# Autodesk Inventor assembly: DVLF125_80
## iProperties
Created: 2010-04
Part Number: DVLF125_80
Document SubType Name: Assembly
Designer: TB
Mass: 5505.55 g
Surface Area: 5358.15 cm^2
Volume: 5505.55 cm^3
Density: 1 g/cm^3
Description: KM DVLF 125/80 - 100 mm
Slaglengde: 100.000 mm
Author: TB
